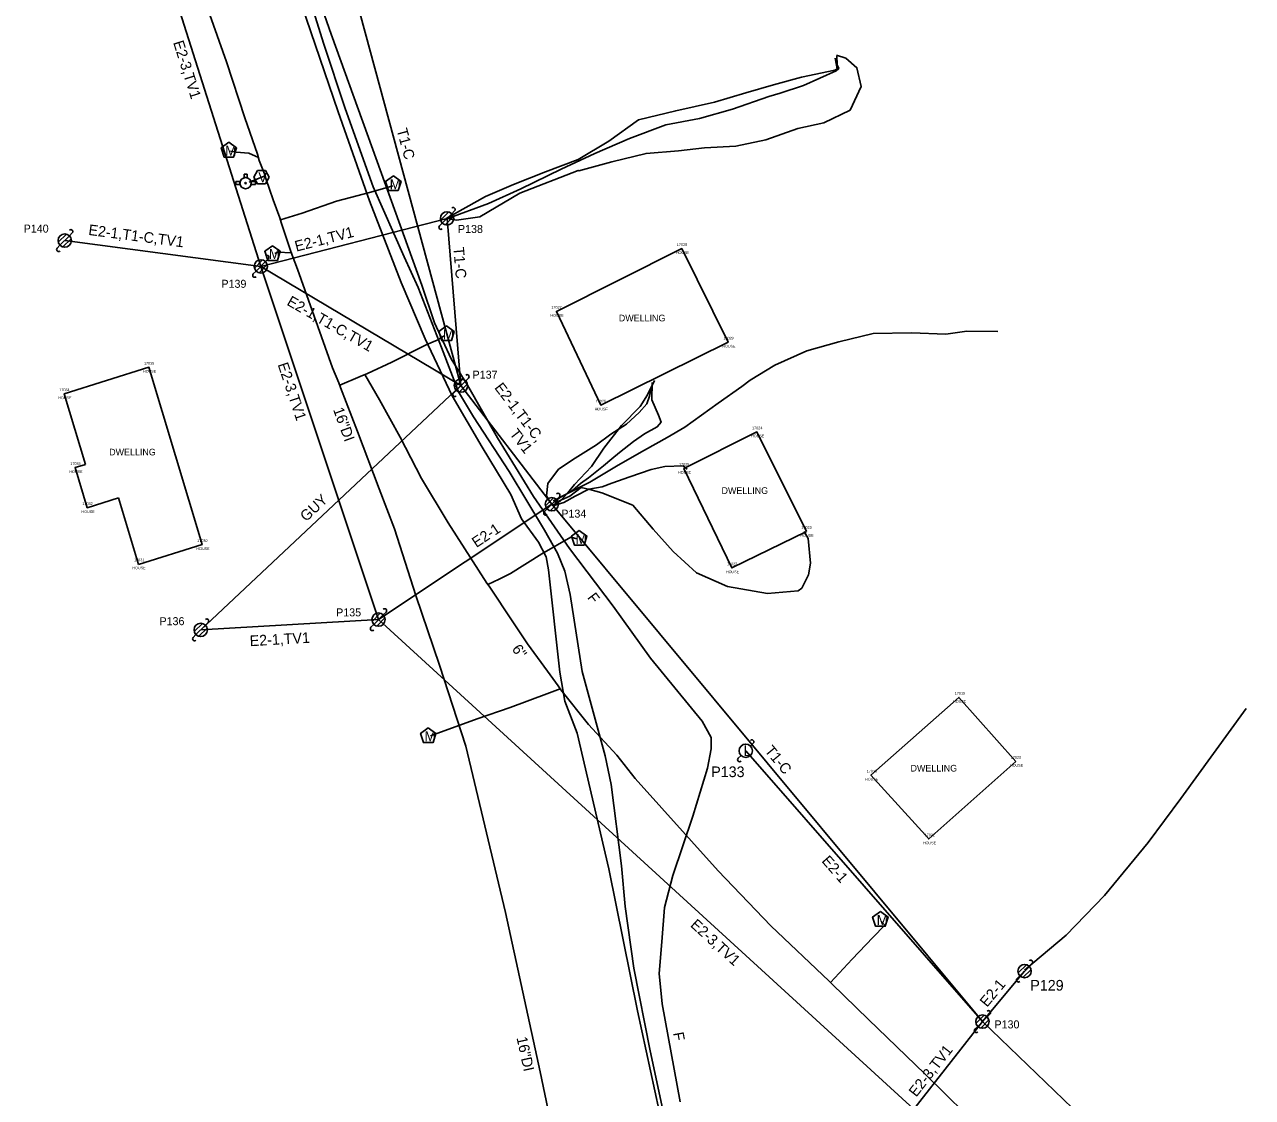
# Model space of a CAD drawing. Extents: x 1614474 to 1865144, y 1098877 to 1212550.
# Drawn here: x 1754886.6 to 1755346.9, y 1170509.7 to 1170911.9 of the extents above; entities that cross this region are included whole.
import ezdxf

# ---------------------------------------------------------------- set-up
doc = ezdxf.new("R2010")
doc.units = 0
for name, color, linetype in [('RD_EX_Bldg', 7, 'Continuous'), ('RD_EX_Bldg_TxCode', 7, 'Continuous'), ('RD_EX_SU_Elec', 7, 'Continuous'), ('RD_EX_SU_H2O', 7, 'Continuous'), ('RD_EX_SU_Ovhd', 7, 'Continuous'), ('RD_EX_SU_Pole', 7, 'Continuous'), ('RD_EX_SU_Telecom', 7, 'Continuous'), ('RD_EX_SU_TX_H2O', 7, 'Continuous'), ('RD_EX_SU_TX_Pole', 7, 'Continuous'), ('RD_EX_SU_TX_Telecom', 7, 'Continuous'), ('RD_SMD_Locator', 7, 'Continuous')]:
    doc.layers.add(name, color=color, linetype=linetype)

# ---------------------------------------------------------------- blocks, each defined once
blk = doc.blocks.new('SUE_PP')
at = {"layer": 'RD_EX_SU_Pole'}
for p, q in [((-2.41, -0.65), (0.65, 2.41)), ((-1.77, -1.77), (1.77, 1.77)), ((-0.65, -2.41), (2.41, 0.65)), ((1.77, 1.77), (2.83, 2.83)), ((-2.83, -2.83), (-1.77, -1.77))]:
    blk.add_line(p, q, dxfattribs=at)
blk.add_circle((0, 0), 2.5, dxfattribs=at)
for centre, start, end in [((2.3, 3.36), 315, 135), ((-2.3, -3.36), 135, 315)]:
    blk.add_arc(centre, 0.75, start, end, dxfattribs=at)

msp = doc.modelspace()

# ---------------------------------------------------------------- linework, layer by layer
at = {"layer": 'RD_EX_Bldg'}
for p, q in [((1755085.98, 1170804.38), (1755132.98, 1170827.93)), ((1755132.98, 1170827.93), (1755150.42, 1170792.85)), ((1755085.98, 1170804.38), (1755102.6, 1170769.24)), ((1755102.6, 1170769.24), (1755150.42, 1170792.85)), ((1754901.47, 1170773.49), (1754933.21, 1170783.45)), ((1754933.21, 1170783.45), (1754953.22, 1170716.93)), ((1754901.47, 1170773.49), (1754909.43, 1170747.02)), ((1755133.8, 1170745.54), (1755161.2, 1170759.2)), ((1755161.2, 1170759.2), (1755179.7, 1170721.9)), ((1754905.58, 1170745.82), (1754909.43, 1170747.02)), ((1754905.58, 1170745.82), (1754910.1, 1170730.79)), ((1755151.77, 1170708.24), (1755133.8, 1170745.54)), ((1754910.1, 1170730.79), (1754921.81, 1170734.47)), ((1754921.81, 1170734.47), (1754929.34, 1170709.44)), ((1755179.7, 1170721.9), (1755151.77, 1170708.24)), ((1754929.34, 1170709.44), (1754953.22, 1170716.93)), ((1755203.92, 1170630.5), (1755236.9, 1170659.67)), ((1755236.9, 1170659.67), (1755258.23, 1170635.67)), ((1755258.23, 1170635.67), (1755225.61, 1170606.61)), ((1755225.61, 1170606.61), (1755203.92, 1170630.5))]:
    msp.add_line(p, q, dxfattribs=at)
at = {"layer": 'RD_EX_SU_Elec'}
for points in [[(1755044.7, 1170839.23), (1755059.42, 1170847.52), (1755069.97, 1170851.99), (1755081.97, 1170856.73), (1755094.15, 1170861.35), (1755105.68, 1170868.24), (1755116.83, 1170876.23), (1755130.76, 1170879.59), (1755145.27, 1170882.79), (1755157.04, 1170886.35), (1755167.37, 1170889.4), (1755177.92, 1170892.19), (1755190.42, 1170894.89), (1755191.27, 1170895.37), (1755190.53, 1170899.32)], [(1755084.76, 1170733.42), (1755089.15, 1170735.61), (1755098.48, 1170740.34), (1755109.16, 1170746.7), (1755118.99, 1170752.35), (1755127.51, 1170757.14), (1755134.1, 1170760.96), (1755146.67, 1170769.95), (1755155.55, 1170776.25), (1755158.59, 1170778.65), (1755167.83, 1170784.2), (1755179.88, 1170789.61), (1755191.9, 1170793.03), (1755204.81, 1170796.12), (1755219.13, 1170796.38), (1755232.05, 1170795.84), (1755239.93, 1170796.97), (1755251.49, 1170796.86)], [(1755084.91, 1170731.92), (1755087.35, 1170733.19), (1755090.32, 1170736.35), (1755092.73, 1170739.5), (1755099.15, 1170746.28), (1755103.76, 1170753.16), (1755110.39, 1170761.57), (1755117.38, 1170768.69), (1755120.2, 1170773.08), (1755122.8, 1170778.49)], [(1755084.11, 1170731.83), (1755085.97, 1170731.91), (1755088.75, 1170732.77), (1755092.98, 1170735.1), (1755098.13, 1170737.74), (1755103.12, 1170738.67), (1755106.73, 1170740), (1755113.51, 1170742.36), (1755121.53, 1170745.15), (1755126.71, 1170746.19), (1755133.52, 1170746.54), (1755135.08, 1170745.23)], [(1755261.47, 1170557.34), (1755277.07, 1170570.46), (1755291.51, 1170585.36), (1755307.86, 1170605.28), (1755320.07, 1170621.78), (1755344.55, 1170655.55)]]:
    msp.add_lwpolyline(points, dxfattribs=at)
at = {"layer": 'RD_EX_SU_H2O'}
for p, q in [((1754967.44, 1170853.08), (1754965.8, 1170853.08)), ((1754965.8, 1170853.08), (1754965.8, 1170852.03)), ((1754968.97, 1170855.86), (1754968.97, 1170854.52)), ((1754970.02, 1170855.86), (1754968.97, 1170855.86)), ((1754970.02, 1170854.49), (1754970.02, 1170855.86)), ((1754970.88, 1170852.82), (1754976.78, 1170855.16)), ((1754973.15, 1170853.08), (1754971.46, 1170853.08)), ((1754973.15, 1170852.03), (1754973.15, 1170853.08)), ((1754965.8, 1170852.03), (1754967.4, 1170852.03)), ((1754971.5, 1170852.03), (1754973.15, 1170852.03))]:
    msp.add_line(p, q, dxfattribs=at)
for points in [[(1754956.06, 1170915.61), (1754962.38, 1170897.97), (1754969.17, 1170876.92), (1754973.9, 1170863.31), (1754974.6, 1170860.97), (1754976.54, 1170856.02), (1754977.05, 1170854.22), (1754979.81, 1170846.24), (1754982.34, 1170839.52), (1754982.8, 1170837.72), (1754986.07, 1170828.02), (1754986.99, 1170825.47), (1754988.93, 1170820.19), (1755002.08, 1170783.29), (1755004.4, 1170777.61), (1755005.1, 1170775.84), (1755011.46, 1170759.4), (1755019.59, 1170737.92), (1755025.36, 1170722.87), (1755033.31, 1170697.84), (1755042.14, 1170671.77)], [(1754963.77, 1170864.49), (1754965.97, 1170864.08), (1754970.66, 1170863.71), (1754974.26, 1170862.11)], [(1754982.53, 1170838.76), (1754990.75, 1170841.23), (1755003.57, 1170845.66), (1755016.43, 1170849.11), (1755024.71, 1170851.52)], [(1754986.66, 1170826.38), (1754981.58, 1170826.63), (1754980.39, 1170826.13)], [(1755004.79, 1170776.74), (1755012.45, 1170780.01), (1755015.18, 1170781.14), (1755024.31, 1170785.39), (1755037.39, 1170791.92), (1755041.3, 1170793.55), (1755044.15, 1170795.36)], [(1755014.24, 1170780.75), (1755019.67, 1170771.18), (1755027.37, 1170757.25), (1755035.4, 1170741.69), (1755045.44, 1170725.1), (1755059.91, 1170702.52), (1755060.75, 1170701.38), (1755069.67, 1170687.97), (1755075.12, 1170679.72), (1755082.62, 1170669.44), (1755086.66, 1170663.95), (1755087.69, 1170662.44), (1755098.04, 1170649.52), (1755108.67, 1170637.95), (1755115.51, 1170629.29), (1755146.69, 1170594.66), (1755166.41, 1170574.06), (1755188.2, 1170553.24), (1755189.2, 1170552.26), (1755202.99, 1170538.84), (1755224.11, 1170518.52), (1755246.97, 1170496)], [(1755060.31, 1170701.97), (1755064.52, 1170704.03), (1755068.81, 1170706.14), (1755080.57, 1170713.54), (1755091.39, 1170719.75), (1755093.83, 1170719.16)], [(1755042.14, 1170671.77), (1755052.06, 1170641.32), (1755066.9, 1170578.97), (1755079.96, 1170519.29), (1755092.63, 1170458.3), (1755105.45, 1170397.86), (1755116.43, 1170325.12), (1755123.37, 1170260.52), (1755129.9, 1170197.98), (1755130.76, 1170187.84), (1755130.94, 1170186.34), (1755135.98, 1170128.29), (1755137.6, 1170105.08), (1755122.59, 1170093.04)], [(1755038.81, 1170645.21), (1755056.35, 1170651.65), (1755068.64, 1170655.9), (1755082.42, 1170661), (1755087.41, 1170662.85)], [(1755188.74, 1170552.71), (1755196.87, 1170561.52), (1755204.69, 1170569.58), (1755209.12, 1170574.23), (1755207.59, 1170575.88)]]:
    msp.add_lwpolyline(points, dxfattribs=at)
for points in [[(1754963.21, 1170867.78), (1754960.3, 1170865.67), (1754961.41, 1170862.26), (1754965, 1170862.26), (1754966.11, 1170865.67)], [(1754978.33, 1170854.71), (1754976.89, 1170857.21), (1754974, 1170857.21), (1754972.56, 1170854.71), (1754974, 1170852.21), (1754976.89, 1170852.21)], [(1755024.87, 1170855.24), (1755021.97, 1170853.13), (1755023.08, 1170849.72), (1755026.66, 1170849.72), (1755027.77, 1170853.13)], [(1754979.59, 1170829.03), (1754976.69, 1170826.92), (1754977.8, 1170823.51), (1754981.38, 1170823.51), (1754982.49, 1170826.92)], [(1755044.83, 1170798.96), (1755041.93, 1170796.85), (1755043.04, 1170793.44), (1755046.62, 1170793.44), (1755047.73, 1170796.85)], [(1755094.56, 1170722.28), (1755091.66, 1170720.17), (1755092.76, 1170716.76), (1755096.35, 1170716.76), (1755097.46, 1170720.17)], [(1755037.96, 1170648.25), (1755035.06, 1170646.14), (1755036.17, 1170642.73), (1755039.75, 1170642.73), (1755040.86, 1170646.14)], [(1755207.46, 1170579.4), (1755204.56, 1170577.29), (1755205.67, 1170573.88), (1755209.26, 1170573.88), (1755210.36, 1170577.29)]]:
    msp.add_lwpolyline(points, close=True, dxfattribs=at)
for radius in [2.1, 0.263]:
    msp.add_circle((1754969.45, 1170852.47), radius, dxfattribs=at)
for start, end in [(163.3387, 192.315), (74.2455, 103.2128), (347.685, 16.6613)]:
    msp.add_arc((1754969.45, 1170852.47), 2.1, start, end, dxfattribs=at)
at = {"layer": 'RD_EX_SU_Ovhd'}
for p, q in [((1754936.53, 1170943.16), (1754975.2, 1170821.28)), ((1755009.84, 1170925.6), (1755050.22, 1170776.56)), ((1754975.2, 1170821.28), (1755045, 1170839.26)), ((1755045, 1170839.26), (1755050.22, 1170776.56)), ((1754901.67, 1170830.96), (1754975.2, 1170821.28)), ((1754975.2, 1170821.28), (1755050.22, 1170776.56)), ((1754975.2, 1170821.28), (1755019.3, 1170688.81)), ((1754952.64, 1170684.97), (1755050.22, 1170776.56)), ((1755050.22, 1170776.56), (1755084.28, 1170732.08)), ((1755019.3, 1170688.81), (1755084.28, 1170732.08)), ((1755084.28, 1170732.08), (1755245.71, 1170538.1)), ((1754952.64, 1170684.97), (1755019.3, 1170688.81)), ((1755019.3, 1170688.81), (1755220.03, 1170505.23)), ((1755156.98, 1170639.65), (1755245.71, 1170538.1)), ((1755245.71, 1170538.1), (1755261.53, 1170557.04)), ((1755220.03, 1170505.23), (1755245.71, 1170538.1)), ((1755245.71, 1170538.1), (1755346.94, 1170440.97))]:
    msp.add_line(p, q, dxfattribs=at)
at = {"layer": 'RD_EX_SU_Pole'}
for p, q in [((1755042.58, 1170838.61), (1755045.65, 1170841.68)), ((1755043.23, 1170837.49), (1755046.77, 1170841.03)), ((1755044.35, 1170836.85), (1755047.41, 1170839.91)), ((1755046.77, 1170841.03), (1755047.83, 1170842.09)), ((1755042.17, 1170836.43), (1755043.23, 1170837.49)), ((1755081.87, 1170731.43), (1755084.93, 1170734.49)), ((1755082.51, 1170730.31), (1755086.05, 1170733.84)), ((1755086.05, 1170733.84), (1755087.11, 1170734.9)), ((1755081.45, 1170729.25), (1755082.51, 1170730.31)), ((1755083.63, 1170729.66), (1755086.7, 1170732.72)), ((1755158.75, 1170641.42), (1755159.81, 1170642.48)), ((1755154.15, 1170636.83), (1755155.21, 1170637.89))]:
    msp.add_line(p, q, dxfattribs=at)
for centre in [(1755045, 1170839.26), (1755084.28, 1170732.08), (1755156.98, 1170639.65)]:
    msp.add_circle(centre, 2.5, dxfattribs=at)
for centre, start, end in [((1755047.3, 1170842.62), 315, 135), ((1755042.7, 1170835.9), 135, 315), ((1755086.58, 1170735.43), 315, 135), ((1755081.98, 1170728.72), 135, 315), ((1755159.28, 1170643.01), 315, 135), ((1755154.68, 1170636.3), 135, 315)]:
    msp.add_arc(centre, 0.75, start, end, dxfattribs=at)
at = {"layer": 'RD_EX_SU_Telecom'}
for points in [[(1754967.13, 1170994.05), (1754974.43, 1170968.95), (1754987.04, 1170929.46), (1755004.13, 1170879.16), (1755015.94, 1170845.8), (1755027.84, 1170815.17), (1755036.74, 1170794.1), (1755046.9, 1170772.73), (1755058.13, 1170753.54), (1755068.96, 1170735.75), (1755072.88, 1170726.57), (1755079.23, 1170717.91), (1755082.2, 1170712.4), (1755082.99, 1170707.43), (1755087.24, 1170669.18), (1755089.17, 1170658.27), (1755093.84, 1170646.29), (1755105.7, 1170595.36), (1755111, 1170568.73), (1755116.38, 1170542.14), (1755124.51, 1170504.65), (1755130.68, 1170470.03), (1755139.68, 1170422.81)], [(1754989.66, 1170942.34), (1755001.61, 1170908.39), (1755035.52, 1170814.23), (1755040.32, 1170800.04), (1755046.58, 1170786.61), (1755052.71, 1170776.7), (1755063.97, 1170756.98), (1755077.38, 1170735), (1755090.96, 1170715.53), (1755107.27, 1170693.89), (1755121.25, 1170674.35), (1755140.61, 1170650.74), (1755144.01, 1170644.65), (1755144.02, 1170640.39), (1755142.64, 1170633.11), (1755137.09, 1170615.19), (1755129.59, 1170592.91), (1755126.56, 1170580.85), (1755125.53, 1170568), (1755124.55, 1170556.1), (1755125.66, 1170544.73), (1755132.36, 1170508.03)], [(1754990.73, 1170930.67), (1754998.66, 1170905.01), (1755006.82, 1170880.46), (1755017.33, 1170851.11), (1755028.92, 1170824.86), (1755034.21, 1170813.32), (1755042.89, 1170790.87), (1755049.31, 1170774.25), (1755054.9, 1170764.86), (1755068.27, 1170744.38), (1755081.53, 1170722.42), (1755086.38, 1170713.73), (1755089.14, 1170706.97), (1755091.1, 1170698.27), (1755095.61, 1170669.4), (1755104.32, 1170637.7), (1755106.48, 1170627.02), (1755110.45, 1170596.46), (1755111.79, 1170581.3), (1755115.03, 1170558.13), (1755121.12, 1170527.09), (1755125.84, 1170504.97)], [(1755044.96, 1170839.04), (1755060.53, 1170844.8), (1755072.63, 1170850.4), (1755087.77, 1170857.76), (1755100.36, 1170863.53), (1755113.43, 1170869.18), (1755127.03, 1170874.33), (1755139.59, 1170876.74), (1755151.97, 1170880.24), (1755165.7, 1170884.94), (1755169.93, 1170886.23), (1755178.63, 1170889.07), (1755190.93, 1170894.56), (1755191.88, 1170895.42), (1755191.31, 1170896.87), (1755191.14, 1170900.26)], [(1755045.16, 1170839.16), (1755048.5, 1170838.63), (1755057.3, 1170839.89), (1755072.32, 1170848.71), (1755094.13, 1170857.27), (1755094.38, 1170857.14), (1755106.77, 1170860.49), (1755119.62, 1170863.63), (1755131.82, 1170864.59), (1755141.51, 1170865.71), (1755153.27, 1170866.37), (1755164.52, 1170868.73), (1755176.53, 1170872.91), (1755186.28, 1170875.11), (1755196.1, 1170879.88), (1755200.25, 1170888.75), (1755198.69, 1170895.74), (1755194.47, 1170899.35), (1755190.97, 1170900.47)], [(1755083.67, 1170732.7), (1755082.24, 1170735.28), (1755082.78, 1170739.91), (1755086.8, 1170745.28), (1755093.03, 1170749.4), (1755101, 1170754.35), (1755106.35, 1170758.4), (1755112.23, 1170762.1), (1755116.99, 1170766.45), (1755119.87, 1170769.79), (1755120.86, 1170772.65), (1755121.48, 1170775.76)], [(1755085.29, 1170733.01), (1755087.12, 1170734.51), (1755089.36, 1170735.75), (1755091.98, 1170737.24), (1755094.99, 1170739.85), (1755098.08, 1170742.02), (1755103.7, 1170746.53), (1755106.76, 1170749.14), (1755109.65, 1170751.43), (1755114.88, 1170755.64), (1755119.02, 1170758.45), (1755123.8, 1170761.07), (1755125.26, 1170762.82), (1755124.22, 1170765.54), (1755121.8, 1170771.17), (1755121.92, 1170777.71)], [(1755085.41, 1170732.59), (1755091.05, 1170735.15), (1755095.3, 1170738.34), (1755098.54, 1170737.66), (1755103, 1170736.4), (1755114.6, 1170731.7), (1755122.27, 1170722.73), (1755129.72, 1170714.33), (1755138.51, 1170706.38), (1755150.14, 1170701.27), (1755165.19, 1170698.57), (1755176.63, 1170699.59), (1755178.04, 1170700.64), (1755180.49, 1170705.64), (1755181.24, 1170710.01), (1755180.4, 1170719.19), (1755178.9, 1170721.85)]]:
    msp.add_lwpolyline(points, dxfattribs=at)
at = {"layer": 'RD_SMD_Locator'}
for centre in [(1755132.98, 1170827.93), (1755085.98, 1170804.38), (1755150.42, 1170792.85), (1754933.21, 1170783.45), (1754901.47, 1170773.49), (1755102.6, 1170769.24), (1755161.2, 1170759.2), (1754905.58, 1170745.82), (1755133.8, 1170745.54), (1754910.14, 1170730.8), (1755179.7, 1170721.9), (1754953.22, 1170716.93), (1754929.25, 1170709.74), (1755151.77, 1170708.24), (1755236.9, 1170659.67), (1755258.23, 1170635.67), (1755203.92, 1170630.5), (1755225.61, 1170606.61)]:
    msp.add_circle(centre, 0.001, dxfattribs=at)

# ---------------------------------------------------------------- block references
at = {"layer": 'RD_EX_SU_Pole'}
for p in [(1754901.67, 1170830.96), (1754975.2, 1170821.28), (1755050.22, 1170776.56), (1755019.3, 1170688.81), (1754952.64, 1170684.97), (1755261.53, 1170557.04), (1755245.71, 1170538.1)]:
    msp.add_blockref('SUE_PP', p, dxfattribs=at)

# ---------------------------------------------------------------- texts
at = {"layer": 'RD_EX_Bldg'}
for p in [(1755109.4, 1170800.64), (1754918.34, 1170750.39), (1755147.91, 1170735.96), (1755218.76, 1170631.87)]:
    msp.add_text('DWELLING', height=2.5, dxfattribs=at).set_placement(p)
at = {"layer": 'RD_EX_Bldg_TxCode'}
for s, p in [('HOUSE', (1755130.79, 1170825.93)), ('17028', (1755131.15, 1170828.93)), ('HOUSE', (1755083.79, 1170802.38)), ('17027', (1755084.14, 1170805.38)), ('17029', (1755148.58, 1170793.85)), ('HOUSE', (1755148.22, 1170790.85)), ('17035', (1754931.38, 1170784.45)), ('HOUSE', (1754931.02, 1170781.45)), ('17034', (1754899.63, 1170774.49)), ('HOUSE', (1754899.28, 1170771.49)), ('17026', (1755100.74, 1170770.24)), ('HOUSE', (1755100.4, 1170767.24)), ('17024', (1755159.36, 1170760.2)), ('HOUSE', (1755159.01, 1170757.2)), ('17033', (1754903.75, 1170746.82)), ('17025', (1755131.96, 1170746.54)), ('HOUSE', (1754903.39, 1170743.82)), ('HOUSE', (1755131.61, 1170743.54)), ('HOUSE', (1754907.95, 1170728.8)), ('17032', (1754908.31, 1170731.8)), ('HOUSE', (1755177.5, 1170719.9)), ('17023', (1755177.86, 1170722.9)), ('HOUSE', (1754951.03, 1170714.93)), ('17030', (1754951.34, 1170717.93)), ('17031', (1754927.7, 1170710.74)), ('HOUSE', (1754927.06, 1170707.74)), ('HOUSE', (1755149.57, 1170706.24)), ('17022', (1755149.93, 1170709.24)), ('17019', (1755235.35, 1170660.67)), ('HOUSE', (1755234.71, 1170657.67)), ('17020', (1755256.36, 1170636.67)), ('17018', (1755202.37, 1170631.5)), ('HOUSE', (1755256.04, 1170633.67)), ('HOUSE', (1755201.72, 1170628.5)), ('HOUSE', (1755223.41, 1170604.61)), ('17021', (1755224.05, 1170607.61))]:
    msp.add_text(s, height=1, dxfattribs=at).set_placement(p)
at = {"layer": 'RD_EX_SU_H2O'}
for s, p in [('M', (1754961.84, 1170862.74)), ('V', (1754974.24, 1170852.83)), ('M', (1755023.5, 1170850.2)), ('M', (1754978.22, 1170823.99)), ('M', (1755043.46, 1170793.92)), ('M', (1755093.19, 1170717.23)), ('M', (1755036.59, 1170643.21)), ('M', (1755206.09, 1170574.35))]:
    msp.add_text(s, height=3.75, dxfattribs=at).set_placement(p)
at = {"layer": 'RD_EX_SU_Ovhd'}
for s, rotation, p in [('E2-3,TV1', 287.6005, (1754942.27, 1170905.23)), ('T1-C', 285.1581, (1755026.07, 1170872.47)), ('E2-1,T1-C,TV1', 352.502, (1754910.39, 1170833.08)), ('E2-1,TV1', 14.446, (1754988.49, 1170826.77)), ('T1-C', 274.76, (1755047.34, 1170828.38)), ('E2-1,T1-C,TV1', 330.2978, (1754984.64, 1170806.97)), ('E2-3,TV1', 288.4116, (1754981.46, 1170784.49)), ('E2-1,T1-C,', 307.4385, (1755062.58, 1170775.73)), ('TV1', 307.4385, (1755068.23, 1170758.49)), ('GUY', 43.187, (1754992.19, 1170725.35)), ('E2-1', 33.6558, (1755056.01, 1170715.66)), ('E2-1,TV1', 3.2962, (1754971.13, 1170678.84)), ('T1-C', 309.7661, (1755163.86, 1170639.57)), ('E2-1', 311.1414, (1755185.22, 1170598.21)), ('E2-3,TV1', 317.5559, (1755135.96, 1170573.98)), ('E2-1', 50.1424, (1755247.43, 1170543.28)), ('E2-3,TV1', 52.0038, (1755220.9, 1170509.58))]:
    msp.add_text(s, height=4, rotation=rotation, dxfattribs=at).set_placement(p)
at = {"layer": 'RD_EX_SU_Pole'}
msp.add_text('L', height=4, dxfattribs=at).set_placement((1755156.12, 1170637.65))
at = {"layer": 'RD_EX_SU_TX_H2O'}
for s, rotation, p in [('16"DI', 290.062, (1755002.22, 1170767.58)), ('6"', 306.1361, (1755069.13, 1170677.75)), ('16"DI', 282.3354, (1755071.03, 1170532.01))]:
    msp.add_text(s, height=4, rotation=rotation, dxfattribs=at).set_placement(p)
at = {"layer": 'RD_EX_SU_TX_Pole'}
for s, height, p in [('P140', 3, (1754886.28, 1170833.93)), ('P138', 3, (1755049.09, 1170833.79)), ('P139', 3, (1754960.41, 1170813.24)), ('P137', 3, (1755054.57, 1170779.17)), ('P134', 3, (1755087.84, 1170727.07)), ('P135', 3, (1755003.42, 1170690.04)), ('P136', 3, (1754937.19, 1170686.74)), ('P133', 4, (1755144.04, 1170629.77)), ('P129', 4, (1755263.67, 1170549.72)), ('P130', 3, (1755250.23, 1170535.56))]:
    msp.add_text(s, height=height, dxfattribs=at).set_placement(p)
at = {"layer": 'RD_EX_SU_TX_Telecom'}
for rotation, p in [(306.9994, (1755097.39, 1170697.03)), (280.3457, (1755129.69, 1170533.82))]:
    msp.add_text('F', height=4, rotation=rotation, dxfattribs=at).set_placement(p)

doc.saveas('drawing.dxf')
